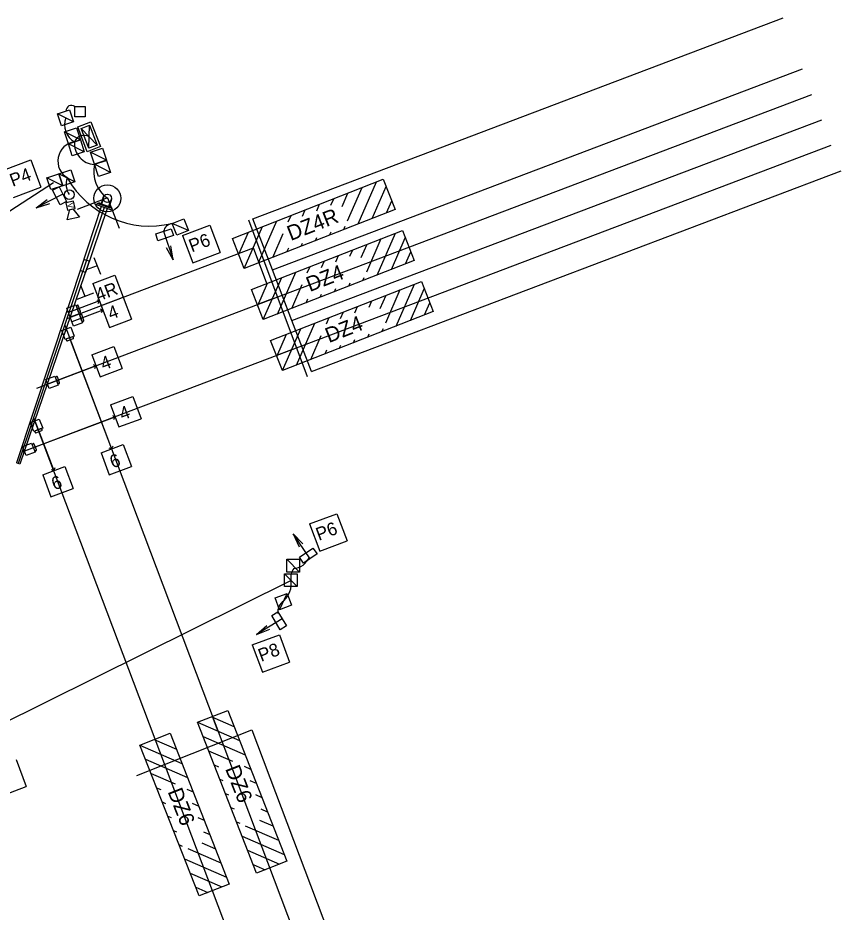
# Model space of a CAD drawing. Extents: x 510435 to 510719, y 1315254 to 1315553.
# Drawn here: x 510566.7 to 510719.1, y 1315365 to 1315530.6 of the extents above; entities that cross this region are included whole.
import ezdxf

# ---------------------------------------------------------------- set-up
doc = ezdxf.new("R2010")
doc.units = 0
for name, color, linetype in [('ConduitDB', 7, 'Continuous'), ('ControllerB', 7, 'Continuous'), ('Default', 7, 'Continuous'), ('DetectorVeh', 7, 'Continuous'), ('NonPlottingEle_dp', 7, 'Continuous'), ('OverheadStr', 7, 'Continuous'), ('Pedestal', 7, 'Continuous'), ('PedHead', 7, 'Continuous'), ('PMStripe24W', 7, 'Continuous'), ('PoleConc', 7, 'Continuous'), ('PoleFound', 7, 'Continuous'), ('PullBox', 7, 'Continuous'), ('SignalHead', 7, 'Continuous'), ('SignSupport', 7, 'Continuous'), ('TextNotes', 7, 'Continuous')]:
    doc.layers.add(name, color=color, linetype=linetype)

# ---------------------------------------------------------------- blocks, each defined once
blk = doc.blocks.new('VSVideoCamera')
at = {"layer": 'DetectorVeh'}
blk.add_line((0, -0.59), (0, 0.59), dxfattribs=at)
blk.add_lwpolyline([(0, 1.41), (-2.81, 1.41), (-2.81, -1.41), (0, -1.41)], close=True, dxfattribs=at)
blk.add_lwpolyline([(0, 0.59), (3.52, 2.34), (3.52, -2.34), (0, -0.59)], dxfattribs=at)
blk.add_text('V', height=2.25, dxfattribs=at).set_placement((-2.41, -1.12))
blk = doc.blocks.new('SignalPoles_cel_SPoleConcN02')
at = {"layer": 'PoleConc'}
blk.add_lwpolyline([(-0.25, -0.25), (-0.25, 0.25), (0.25, 0.25), (0.25, -0.25)], close=True, dxfattribs=at)
blk = doc.blocks.new('MastArmD4')
at = {"layer": 'OverheadStr'}
for p, q in [((0.25, 1.5), (0, 1.5)), ((0, 1.5), (0, -1.5)), ((0, -1.04), (0, 1.04)), ((0.25, 1.5), (0.25, -1.5)), ((0.25, 0.58), (11.7, 0.52)), ((9.7, 0.54), (46, 0.33)), ((9.7, 0.54), (9.7, -0.54)), ((11.7, 0.52), (11.7, -0.52)), ((46, 0.33), (46, -0.33)), ((0.25, -1.5), (0, -1.5)), ((0.25, -0.58), (11.7, -0.52)), ((9.7, -0.54), (46, -0.33))]:
    blk.add_line(p, q, dxfattribs=at)

msp = doc.modelspace()

# ---------------------------------------------------------------- linework, layer by layer
at = {"layer": 'ConduitDB'}
for p, q in [((510521.96, 1315467.05), (510573.34, 1315500.1)), ((510553, 1315394.55), (510617.23, 1315426.44))]:
    msp.add_line(p, q, dxfattribs=at)
at = {"layer": 'ControllerB'}
for p, q in [((510577.8, 1315510.41), (510580.25, 1315511.35)), ((510578.43, 1315510.13), (510579.97, 1315510.71)), ((510579.85, 1315506.45), (510579.97, 1315510.71)), ((510579.97, 1315510.71), (510581.38, 1315507.04)), ((510580.25, 1315511.35), (510582.01, 1315506.76)), ((510579.56, 1315505.81), (510577.8, 1315510.41)), ((510578.43, 1315510.13), (510581.38, 1315507.04)), ((510579.85, 1315506.45), (510578.43, 1315510.13)), ((510582.01, 1315506.76), (510579.56, 1315505.81)), ((510581.38, 1315507.04), (510579.85, 1315506.45))]:
    msp.add_line(p, q, dxfattribs=at)
at = {"layer": 'Default'}
for p, q in [((510627.77, 1315493.02), (510630.46, 1315499.17)), ((510629.7, 1315492.43), (510633.1, 1315500.2)), ((510632.33, 1315493.46), (510634.9, 1315499.35)), ((510626.74, 1315495.66), (510627.83, 1315498.14)), ((510622.04, 1315494.89), (510622.56, 1315496.08)), ((510624.68, 1315495.92), (510625.2, 1315497.11)), ((510634.96, 1315494.49), (510635.94, 1315496.71)), ((510616.77, 1315492.82), (510617.29, 1315494.01)), ((510619.41, 1315493.86), (510619.93, 1315495.05)), ((510611.26, 1315485.21), (510614.66, 1315492.98)), ((510607.6, 1315486.81), (510609.39, 1315490.92)), ((510608.63, 1315484.18), (510612.03, 1315491.95)), ((510613.9, 1315486.24), (510615.83, 1315490.67)), ((510624.43, 1315490.36), (510624.69, 1315490.96)), ((510627.06, 1315491.4), (510627.33, 1315492)), ((510633.23, 1315482.98), (510636.62, 1315490.75)), ((510621.8, 1315489.33), (510622.06, 1315489.93)), ((510631.3, 1315483.57), (510633.99, 1315489.72)), ((510635.86, 1315484.01), (510638.43, 1315489.89)), ((510616.53, 1315487.27), (510616.86, 1315488.03)), ((510619.16, 1315488.3), (510619.43, 1315488.9)), ((510628.2, 1315486.47), (510628.72, 1315487.66)), ((510630.27, 1315486.2), (510631.36, 1315488.69)), ((510625.57, 1315485.43), (510626.09, 1315486.62)), ((510638.49, 1315485.04), (510639.46, 1315487.26)), ((510620.3, 1315483.37), (510620.82, 1315484.56)), ((510622.94, 1315484.4), (510623.46, 1315485.59)), ((510612.16, 1315474.72), (510615.56, 1315482.5)), ((510614.79, 1315475.75), (510618.19, 1315483.53)), ((510630.59, 1315481.94), (510630.85, 1315482.54)), ((510611.13, 1315477.36), (510612.92, 1315481.47)), ((510617.42, 1315476.79), (510619.36, 1315481.21)), ((510627.96, 1315480.91), (510628.22, 1315481.51)), ((510636.76, 1315473.52), (510640.15, 1315481.3)), ((510622.69, 1315478.85), (510622.95, 1315479.45)), ((510625.33, 1315479.88), (510625.59, 1315480.48)), ((510633.8, 1315476.75), (510634.89, 1315479.23)), ((510634.83, 1315474.12), (510637.52, 1315480.27)), ((510639.39, 1315474.55), (510641.96, 1315480.44)), ((510620.06, 1315477.82), (510620.39, 1315478.58)), ((510631.73, 1315477.01), (510632.25, 1315478.2)), ((510642.02, 1315475.59), (510642.99, 1315477.81)), ((510626.47, 1315474.95), (510626.99, 1315476.14)), ((510629.1, 1315475.98), (510629.62, 1315477.17)), ((510618.32, 1315466.3), (510621.72, 1315474.08)), ((510623.83, 1315473.92), (510624.35, 1315475.11)), ((510615.69, 1315465.27), (510619.08, 1315473.04)), ((510634.12, 1315472.49), (510634.38, 1315473.09)), ((510614.65, 1315467.9), (510616.45, 1315472.01)), ((510620.95, 1315467.33), (510622.89, 1315471.76)), ((510628.85, 1315470.43), (510629.12, 1315471.03)), ((510631.49, 1315471.46), (510631.75, 1315472.06)), ((510623.59, 1315468.36), (510623.92, 1315469.13)), ((510626.22, 1315469.4), (510626.48, 1315469.99)), ((510602.6, 1315401.21), (510606.71, 1315399.41)), ((510599.97, 1315400.18), (510607.74, 1315396.78)), ((510591.95, 1315396.98), (510596.06, 1315395.19)), ((510601, 1315397.55), (510608.78, 1315394.15)), ((510589.32, 1315395.95), (510597.09, 1315392.55)), ((510602.03, 1315394.91), (510606.46, 1315392.98)), ((510590.35, 1315393.32), (510598.13, 1315389.92)), ((510603.06, 1315392.28), (510603.83, 1315391.94)), ((510608.62, 1315392.03), (510609.81, 1315391.51)), ((510591.38, 1315390.68), (510595.81, 1315388.75)), ((510604.1, 1315389.64), (510604.69, 1315389.38)), ((510592.41, 1315388.05), (510593.18, 1315387.72)), ((510609.65, 1315389.4), (510610.84, 1315388.88)), ((510597.97, 1315387.81), (510599.16, 1315387.29)), ((510605.13, 1315387.01), (510605.73, 1315386.75)), ((510610.68, 1315386.77), (510611.87, 1315386.25)), ((510593.45, 1315385.42), (510594.05, 1315385.16)), ((510599, 1315385.17), (510600.19, 1315384.65)), ((510606.16, 1315384.38), (510606.76, 1315384.12)), ((510611.71, 1315384.13), (510612.9, 1315383.61)), ((510594.48, 1315382.78), (510595.08, 1315382.52)), ((510600.03, 1315382.54), (510601.22, 1315382.02)), ((510607.19, 1315381.74), (510607.79, 1315381.48)), ((510611.45, 1315382.07), (510613.93, 1315380.98)), ((510595.51, 1315380.15), (510596.11, 1315379.89)), ((510601.06, 1315379.91), (510602.25, 1315379.39)), ((510608.82, 1315381.03), (510614.97, 1315378.35)), ((510608.22, 1315379.11), (510616, 1315375.71)), ((510596.54, 1315377.52), (510597.14, 1315377.25)), ((510598.17, 1315376.81), (510604.32, 1315374.12)), ((510600.8, 1315377.84), (510603.28, 1315376.75)), ((510609.25, 1315376.48), (510615.14, 1315373.9)), ((510597.57, 1315374.88), (510605.35, 1315371.48)), ((510610.29, 1315373.84), (510612.51, 1315372.87)), ((510598.6, 1315372.25), (510604.49, 1315369.68)), ((510599.64, 1315369.62), (510601.86, 1315368.65))]:
    msp.add_line(p, q, dxfattribs=at)
for points in [[(510606.44, 1315489.76), (510634.37, 1315500.7), (510636.56, 1315495.12), (510608.63, 1315484.18)], [(510609.97, 1315480.31), (510637.9, 1315491.25), (510640.09, 1315485.66), (510612.16, 1315474.72)], [(510613.5, 1315470.86), (510641.43, 1315481.8), (510643.62, 1315476.21), (510615.69, 1315465.27)], [(510605.56, 1315402.37), (510616.5, 1315374.44), (510610.91, 1315372.25), (510599.97, 1315400.18)], [(510594.91, 1315398.14), (510605.85, 1315370.21), (510600.26, 1315368.02), (510589.32, 1315395.95)]]:
    msp.add_lwpolyline(points, close=True, dxfattribs=at)
for centre, radius, start, end in [((510576.63, 1315513.42), 0.972, 50.2933, 185.4121), ((510579, 1315510.77), 3.62, 158.7146, 240.5192), ((510578.97, 1315506.96), 1.87, 59.8376, 159.3625), ((510577.7, 1315504.08), 3.58, 97.6287, 240.6576), ((510581.03, 1315507.29), 3.83, 174.9872, 267.9077), ((510586.92, 1315502.17), 6.17, 167.7927, 233.925), ((510579.06, 1315499.75), 3.4, 160.1632, 213.8023), ((510591.19, 1315509.67), 17.63, 209.8745, 283.3302), ((510595.54, 1315490.65), 1.89, 98.6133, 168.1351), ((510617.61, 1315431.85), 3.22, 272.8933, 339.7985), ((510620.03, 1315426.99), 2.79, 143.811, 188.8839), ((510612.82, 1315425.91), 4.52, 314.3812, 6.8204), ((510617.29, 1315420.59), 2.45, 123.9662, 187.1662)]:
    msp.add_arc(centre, radius, start, end, dxfattribs=at)
at = {"layer": 'NonPlottingEle_dp'}
for p, q in [((510610.22, 1315493.38), (510708.4, 1315530.58)), ((510613.83, 1315483.96), (510711.97, 1315521.15)), ((510570.25, 1315462.05), (510713.7, 1315516.41)), ((510617.44, 1315474.54), (510715.55, 1315511.71)), ((510567.51, 1315450.22), (510717.31, 1315506.99)), ((510621.06, 1315465.12), (510719.12, 1315502.28)), ((510582.72, 1315495.48), (510566.79, 1315448.09)), ((510613.83, 1315483.96), (510610.22, 1315493.38)), ((510575.82, 1315474.95), (510610.34, 1315488.03)), ((510612.81, 1315481.41), (510610.34, 1315488.03)), ((510617.44, 1315474.54), (510613.83, 1315483.96)), ((510581.8, 1315478.17), (510582.43, 1315476.5)), ((510613.87, 1315478.58), (510611.06, 1315477.52)), ((510621.06, 1315465.12), (510617.44, 1315474.54)), ((510575.4, 1315473.7), (510656.98, 1315257.75)), ((510617.4, 1315469.13), (510614.59, 1315468.06)), ((510580.4, 1315468.22), (510581.94, 1315464.13)), ((510569.84, 1315456), (510569.33, 1315454.85)), ((510569.64, 1315456.55), (510646.33, 1315253.52)), ((510603.82, 1315398.47), (510602.76, 1315401.27)), ((510599, 1315394.4), (510610.06, 1315398.79)), ((510610.06, 1315398.79), (510662.51, 1315259.95)), ((510593.17, 1315394.24), (510592.11, 1315397.05)), ((510588.76, 1315390.34), (510599, 1315394.4))]:
    msp.add_line(p, q, dxfattribs=at)
at = {"layer": 'OverheadStr'}
for p, q in [((510582.54, 1315497.44), (510582.12, 1315496.19)), ((510582.58, 1315497.42), (510582.16, 1315496.18)), ((510582.54, 1315497.44), (510582.58, 1315497.42)), ((510581.72, 1315496.32), (510581.67, 1315496.18)), ((510583.97, 1315495.41), (510581.67, 1315496.18)), ((510582.24, 1315496.15), (510581.72, 1315496.32)), ((510582.55, 1315497.07), (510582.21, 1315496.08)), ((510583.48, 1315495.66), (510582.21, 1315496.08)), ((510583.81, 1315496.64), (510583.48, 1315495.66)), ((510584.01, 1315495.55), (510583.5, 1315495.73)), ((510584, 1315496.94), (510583.58, 1315495.7)), ((510584.04, 1315496.93), (510583.62, 1315495.69)), ((510584.04, 1315496.93), (510584, 1315496.94)), ((510584.01, 1315495.55), (510583.97, 1315495.41)), ((510581.32, 1315478.39), (510581.8, 1315478.17)), ((510581.58, 1315477.69), (510581.8, 1315478.17)), ((510577.96, 1315476.09), (510577.55, 1315477.19)), ((510578.31, 1315476.22), (510577.9, 1315477.32)), ((510578.31, 1315476.22), (510577.9, 1315477.32)), ((510581.94, 1315476.72), (510582.43, 1315476.5)), ((510582.21, 1315476.01), (510582.43, 1315476.5)), ((510578.59, 1315474.42), (510578.18, 1315475.52)), ((510578.95, 1315474.55), (510578.53, 1315475.65)), ((510578.95, 1315474.55), (510578.53, 1315475.65)), ((510575.88, 1315470.78), (510576.97, 1315471.2)), ((510576.43, 1315470.99), (510584.06, 1315450.8)), ((510580.67, 1315466.41), (510581.16, 1315466.19)), ((510580.94, 1315465.7), (510581.16, 1315466.19)), ((510574.44, 1315463.01), (510574.03, 1315464.11)), ((510567.99, 1315450.4), (510584.71, 1315456.74)), ((510569.84, 1315456), (510573.37, 1315446.78)), ((510584.22, 1315456.96), (510584.71, 1315456.74)), ((510584.49, 1315456.25), (510584.71, 1315456.74)), ((510570.07, 1315453.77), (510571.16, 1315454.19)), ((510570.15, 1315450.59), (510569.73, 1315451.69)), ((510583.57, 1315451.01), (510584.06, 1315450.8)), ((510584.27, 1315451.29), (510584.06, 1315450.8)), ((510572.88, 1315447), (510573.37, 1315446.78)), ((510573.59, 1315447.27), (510573.37, 1315446.78))]:
    msp.add_line(p, q, dxfattribs=at)
for points in [[(510583.24, 1315496.41), (510582.86, 1315496.54), (510582.59, 1315496.84), (510582.51, 1315497.23), (510582.64, 1315497.61), (510582.94, 1315497.88), (510583.34, 1315497.96), (510583.72, 1315497.83), (510583.98, 1315497.53), (510584.06, 1315497.14), (510583.93, 1315496.75), (510583.63, 1315496.49)], [(510577.44, 1315477.48), (510578.07, 1315475.8), (510576.4, 1315475.17), (510575.77, 1315476.84)], [(510578.07, 1315475.8), (510578.7, 1315474.13), (510577.03, 1315473.5), (510576.4, 1315475.17)], [(510577.13, 1315471.66), (510575.46, 1315471.03), (510574.83, 1315472.7), (510576.5, 1315473.33)], [(510573.57, 1315464.26), (510574.2, 1315462.59), (510572.53, 1315461.96), (510571.89, 1315463.63)], [(510571.32, 1315454.65), (510569.65, 1315454.01), (510569.01, 1315455.68), (510570.68, 1315456.32)], [(510569.27, 1315451.85), (510569.91, 1315450.17), (510568.24, 1315449.54), (510567.6, 1315451.21)]]:
    msp.add_lwpolyline(points, close=True, dxfattribs=at)
for points in [[(510577.55, 1315477.19), (510577.96, 1315476.09)], [(510578.18, 1315475.52), (510578.59, 1315474.42)], [(510576.84, 1315471.55), (510575.74, 1315471.14)], [(510573.67, 1315463.97), (510574.09, 1315462.88)], [(510571.03, 1315454.54), (510569.93, 1315454.12)], [(510569.38, 1315451.56), (510569.8, 1315450.46)]]:
    msp.add_lwpolyline(points, dxfattribs=at)
for centre, radius, start, end in [((510577.79, 1315477.28), 0.115, 20.7534, 140.0731), ((510576.06, 1315478.73), 2.14, 313.9699, 320.0732), ((510577.87, 1315473.95), 2.14, 81.4335, 87.5368), ((510577.87, 1315473.95), 2.14, 81.4335, 87.5368), ((510578.21, 1315476.18), 0.115, 261.4335, 20.7534), ((510578.21, 1315476.18), 0.115, 261.4335, 20.7534), ((510578.42, 1315475.61), 0.115, 20.7534, 140.0731), ((510576.69, 1315477.06), 2.14, 313.9699, 320.0732), ((510578.5, 1315472.28), 2.14, 81.4335, 87.5368), ((510578.5, 1315472.28), 2.14, 81.4335, 87.5368), ((510578.84, 1315474.51), 0.115, 261.4335, 20.7534), ((510578.84, 1315474.51), 0.115, 261.4335, 20.7534), ((510573.6, 1315471.23), 2.14, 351.3341, 357.4374), ((510575.84, 1315470.89), 0.115, 171.3341, 290.6539), ((510578.39, 1315473.03), 2.14, 223.8705, 229.9738), ((510576.93, 1315471.3), 0.115, 290.654, 49.9737), ((510572.19, 1315465.52), 2.14, 313.9699, 320.0732), ((510573.92, 1315464.07), 0.115, 20.7534, 140.0731), ((510574, 1315460.74), 2.14, 81.4335, 87.5368), ((510574.33, 1315462.97), 0.115, 261.4335, 20.7534), ((510572.57, 1315456.03), 2.14, 224.1322, 230.2354), ((510571.12, 1315454.3), 0.115, 290.9156, 50.2354), ((510567.79, 1315454.21), 2.14, 351.5958, 357.699), ((510570.03, 1315453.88), 0.115, 171.5958, 290.9156), ((510567.89, 1315453.1), 2.14, 313.9699, 320.0732), ((510569.63, 1315451.65), 0.115, 20.7534, 140.0731), ((510569.71, 1315448.32), 2.14, 81.4335, 87.5368), ((510570.04, 1315450.55), 0.115, 261.4335, 20.7534)]:
    msp.add_arc(centre, radius, start, end, dxfattribs=at)
at = {"layer": 'Pedestal'}
msp.add_circle((510576.24, 1315497.86), 0.9, dxfattribs=at)
at = {"layer": 'PedHead'}
for p, q in [((510564.04, 1315502.42), (510569.09, 1315504.32)), ((510569.09, 1315504.32), (510570.99, 1315499.26)), ((510565.94, 1315497.36), (510570.99, 1315499.26)), ((510573.16, 1315498.7), (510574.35, 1315499.31)), ((510574.35, 1315499.31), (510575.75, 1315496.61)), ((510575.05, 1315497.96), (510570.1, 1315495.4)), ((510574.56, 1315495.99), (510573.16, 1315498.7)), ((510570.1, 1315495.4), (510572.15, 1315496.96)), ((510570.1, 1315495.4), (510572.62, 1315496.19)), ((510575.75, 1315496.61), (510574.56, 1315495.99)), ((510592.23, 1315490.58), (510595.12, 1315491.55)), ((510593.67, 1315491.07), (510595.46, 1315485.79)), ((510595.12, 1315491.55), (510595.55, 1315490.28)), ((510597.2, 1315490.29), (510602.26, 1315492.19)), ((510602.26, 1315492.19), (510604.16, 1315487.14)), ((510592.66, 1315489.31), (510592.23, 1315490.58)), ((510595.55, 1315490.28), (510592.66, 1315489.31)), ((510597.2, 1315490.29), (510599.1, 1315485.24)), ((510595.46, 1315485.79), (510594.22, 1315488.04)), ((510595.46, 1315485.79), (510595.06, 1315488.4)), ((510599.1, 1315485.24), (510604.16, 1315487.14)), ((510580.58, 1315481.43), (510584.68, 1315482.97)), ((510584.68, 1315482.97), (510586.21, 1315478.88)), ((510580.58, 1315481.43), (510582.12, 1315477.34)), ((510582.12, 1315477.34), (510586.21, 1315478.88)), ((510582.12, 1315477.34), (510586.21, 1315478.88)), ((510586.21, 1315478.88), (510587.75, 1315474.78)), ((510582.12, 1315477.34), (510583.66, 1315473.24)), ((510583.66, 1315473.24), (510587.75, 1315474.78)), ((510580.4, 1315468.22), (510584.49, 1315469.76)), ((510584.49, 1315469.76), (510586.03, 1315465.67)), ((510580.4, 1315468.22), (510581.94, 1315464.13)), ((510581.94, 1315464.13), (510586.03, 1315465.67)), ((510583.88, 1315458.94), (510587.98, 1315460.48)), ((510587.98, 1315460.48), (510589.52, 1315456.38)), ((510583.88, 1315458.94), (510585.42, 1315454.85)), ((510585.42, 1315454.85), (510589.52, 1315456.38)), ((510582.11, 1315450.06), (510586.2, 1315451.6)), ((510586.2, 1315451.6), (510587.74, 1315447.51)), ((510582.11, 1315450.06), (510583.65, 1315445.97)), ((510571.31, 1315446.01), (510575.41, 1315447.55)), ((510571.31, 1315446.01), (510572.85, 1315441.91)), ((510575.41, 1315447.55), (510576.94, 1315443.45)), ((510583.65, 1315445.97), (510587.74, 1315447.51)), ((510572.85, 1315441.91), (510576.94, 1315443.45)), ((510620.72, 1315436.89), (510625.77, 1315438.79)), ((510625.77, 1315438.79), (510627.67, 1315433.74)), ((510620.72, 1315436.89), (510622.62, 1315431.84)), ((510617.69, 1315435.06), (510619.49, 1315433.22)), ((510620.84, 1315430.46), (510617.69, 1315435.06)), ((510617.69, 1315435.06), (510618.78, 1315432.65)), ((510622.62, 1315431.84), (510627.67, 1315433.74)), ((510618.83, 1315430.71), (510621.34, 1315432.43)), ((510622.1, 1315431.33), (510619.59, 1315429.6)), ((510621.34, 1315432.43), (510622.1, 1315431.33)), ((510619.59, 1315429.6), (510618.83, 1315430.71)), ((510613.72, 1315419.92), (510614.86, 1315420.61)), ((510615.3, 1315417.31), (510613.72, 1315419.92)), ((510614.86, 1315420.61), (510616.45, 1315418.01)), ((510615.65, 1315419.31), (510610.89, 1315416.41)), ((510610.89, 1315416.41), (510612.82, 1315418.11)), ((510616.45, 1315418.01), (510615.3, 1315417.31)), ((510610.08, 1315414.49), (510615.14, 1315416.39)), ((510610.89, 1315416.41), (510613.35, 1315417.38)), ((510615.14, 1315416.39), (510617.03, 1315411.33)), ((510610.08, 1315414.49), (510611.98, 1315409.43)), ((510611.98, 1315409.43), (510617.03, 1315411.33)), ((510566.38, 1315393.31), (510568.28, 1315388.26)), ((510563.22, 1315386.36), (510568.28, 1315388.26))]:
    msp.add_line(p, q, dxfattribs=at)
at = {"layer": 'PMStripe24W'}
msp.add_line((510620.35, 1315464.12), (510609.49, 1315493.11), dxfattribs=at)
at = {"layer": 'PoleFound'}
for p, q in [((510581.8, 1315478.17), (510576.08, 1315476.01)), ((510582.43, 1315476.5), (510576.72, 1315474.33)), ((510581.16, 1315466.19), (510572.21, 1315462.79))]:
    msp.add_line(p, q, dxfattribs=at)
at = {"layer": 'PullBox'}
for p, q in [((510574.04, 1315512.85), (510576.27, 1315513.58)), ((510574.77, 1315510.62), (510574.04, 1315512.85)), ((510577, 1315511.35), (510574.04, 1315512.85)), ((510576.27, 1315513.58), (510577, 1315511.35)), ((510577, 1315511.35), (510574.77, 1315510.62)), ((510575.34, 1315509.5), (510577.57, 1315510.23)), ((510576.07, 1315507.27), (510575.34, 1315509.5)), ((510578.29, 1315508), (510575.34, 1315509.5)), ((510577.57, 1315510.23), (510578.29, 1315508)), ((510576.07, 1315507.27), (510578.29, 1315508)), ((510578.29, 1315508), (510576.07, 1315507.27)), ((510576.79, 1315505.05), (510576.07, 1315507.27)), ((510579.02, 1315505.77), (510576.07, 1315507.27)), ((510578.29, 1315508), (510579.02, 1315505.77)), ((510579.02, 1315505.77), (510576.79, 1315505.05)), ((510580.15, 1315505.73), (510582.38, 1315506.46)), ((510580.88, 1315503.5), (510580.15, 1315505.73)), ((510583.11, 1315504.23), (510580.15, 1315505.73)), ((510582.38, 1315506.46), (510583.11, 1315504.23)), ((510583.11, 1315504.23), (510580.88, 1315503.5)), ((510580.89, 1315503.47), (510583.12, 1315504.2)), ((510583.12, 1315504.2), (510583.85, 1315501.97)), ((510574.31, 1315501.73), (510576.53, 1315502.46)), ((510576.53, 1315502.46), (510577.26, 1315500.23)), ((510581.62, 1315501.24), (510580.89, 1315503.47)), ((510583.85, 1315501.97), (510580.89, 1315503.47)), ((510572.08, 1315501), (510574.31, 1315501.73)), ((510572.8, 1315498.78), (510572.08, 1315501)), ((510575.03, 1315499.5), (510572.08, 1315501)), ((510574.31, 1315501.73), (510575.03, 1315499.5)), ((510575.03, 1315499.5), (510574.31, 1315501.73)), ((510577.26, 1315500.23), (510574.31, 1315501.73)), ((510583.85, 1315501.97), (510581.62, 1315501.24)), ((510575.03, 1315499.5), (510572.8, 1315498.78)), ((510577.26, 1315500.23), (510575.03, 1315499.5)), ((510595.26, 1315492.51), (510597.43, 1315493.38)), ((510596.12, 1315490.34), (510595.26, 1315492.51)), ((510598.3, 1315491.2), (510595.26, 1315492.51)), ((510597.43, 1315493.38), (510598.3, 1315491.2)), ((510598.3, 1315491.2), (510596.12, 1315490.34)), ((510616.51, 1315427.99), (510616.51, 1315430.34)), ((510616.51, 1315430.34), (510618.86, 1315430.34)), ((510618.86, 1315427.99), (510616.51, 1315430.34)), ((510618.86, 1315430.34), (510618.86, 1315427.99)), ((510618.86, 1315427.99), (510616.51, 1315427.99)), ((510616.08, 1315425.33), (510616.08, 1315427.67)), ((510616.08, 1315427.67), (510618.42, 1315427.67)), ((510618.42, 1315425.33), (510616.08, 1315427.67)), ((510618.42, 1315427.67), (510618.42, 1315425.33)), ((510618.42, 1315425.33), (510616.08, 1315425.33)), ((510614.36, 1315423.2), (510616.56, 1315424.02)), ((510615.18, 1315421), (510614.36, 1315423.2)), ((510615.18, 1315421), (510616.56, 1315424.02)), ((510616.56, 1315424.02), (510617.38, 1315421.83)), ((510617.38, 1315421.83), (510615.18, 1315421))]:
    msp.add_line(p, q, dxfattribs=at)
at = {"layer": 'SignalHead'}
for p, q in [((510580.79, 1315486.22), (510581.99, 1315483.16)), ((510581.39, 1315484.69), (510579.39, 1315483.91)), ((510579.18, 1315479.02), (510578.4, 1315481.02)), ((510580.71, 1315479.61), (510577.65, 1315478.42))]:
    msp.add_line(p, q, dxfattribs=at)
at = {"layer": 'SignSupport'}
for q in [(510577.71, 1315495.11), (510585.47, 1315491.67)]:
    msp.add_line((510583.31, 1315497.27), q, dxfattribs=at)
at = {"layer": 'TextNotes'}
msp.add_circle((510583.29, 1315497.18), 2.5, dxfattribs=at)
msp.add_circle((510583.29, 1315497.18), 2.5, dxfattribs=at)

# ---------------------------------------------------------------- block references
at = {"layer": 'OverheadStr'}
for name, p, xscale, yscale, rotation in [('MastArmD4', (510582.8, 1315495.74), 1.0928961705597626, 0.9999999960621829, -108.57724603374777), ('VSVideoCamera', (510576.61, 1315495.14), 0.49999999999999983, 0.4999999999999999, -78.0007281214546)]:
    msp.add_blockref(name, p, dxfattribs=dict(at, xscale=xscale, yscale=yscale, rotation=rotation))
at = {"layer": 'PoleConc', "xscale": 3.843400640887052, "yscale": 3.843400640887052, "rotation": 1.131536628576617e-07}
msp.add_blockref('SignalPoles_cel_SPoleConcN02', (510578.21, 1315513.21), dxfattribs=at)

# ---------------------------------------------------------------- texts
at = {"layer": 'Default'}
for s, rotation, p in [('DZ4R', 21.3911, (510617.23, 1315489.26)), ('DZ4 ', 21.3911, (510620.76, 1315479.81)), ('DZ4 ', 21.3911, (510624.29, 1315470.36)), ('DZ6 ', 291.3911, (510605.06, 1315391.58)), ('DZ6 ', 291.3911, (510594.41, 1315387.35))]:
    msp.add_text(s, height=2.8, rotation=rotation, dxfattribs=at).set_placement(p)
at = {"layer": 'PedHead'}
for s, p in [('P4', (510565.75, 1315499.28)), ('P6', (510598.91, 1315487.15)), ('4R', (510581.62, 1315478.07)), ('4', (510583.91, 1315474.66)), ('4', (510582.56, 1315465.31)), ('4', (510586.05, 1315456.03)), ('6', (510584.27, 1315447.15)), ('6', (510573.47, 1315443.1)), ('P6', (510622.43, 1315433.75)), ('P8', (510611.75, 1315411.34))]:
    msp.add_text(s, height=2.4, rotation=20.582, dxfattribs=at).set_placement(p)

doc.saveas('drawing.dxf')
